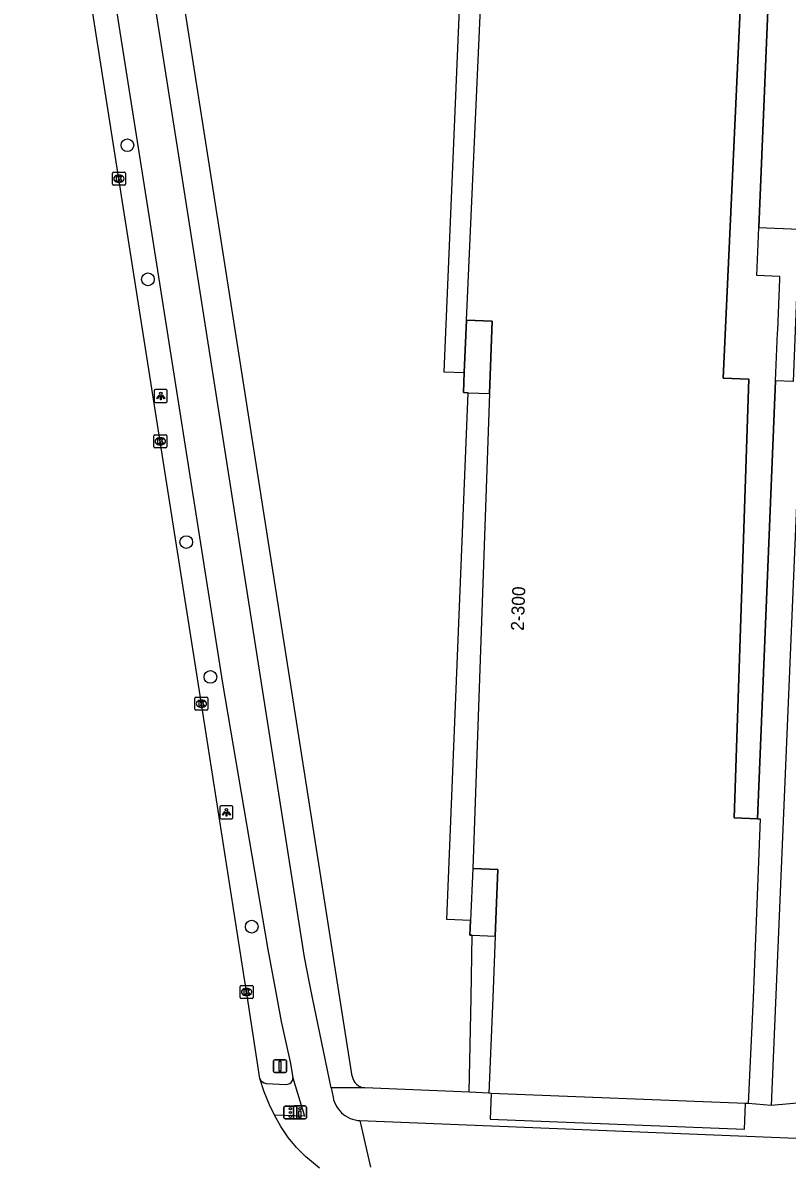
# Model space of a CAD drawing. Extents: x 160891 to 161384, y 386490 to 386907.
# Drawn here: x 160895.5 to 160954.4, y 386737.3 to 386825.1 of the extents above; entities that cross this region are included whole.
import ezdxf

# ---------------------------------------------------------------- set-up
doc = ezdxf.new("R2010")
doc.units = 0
for name, color, linetype in [('IMGEO_Boom', 7, 'Continuous'), ('IMGEO_Drukknoppaal', 7, 'Continuous'), ('IMGEO_Fietspad_gesloten', 7, 'Continuous'), ('IMGEO_Groenvoorziening', 7, 'Continuous'), ('IMGEO_Kolk', 7, 'Continuous'), ('IMGEO_Lichtpunt', 7, 'Continuous'), ('IMGEO_Pand', 7, 'Continuous'), ('IMGEO_Pand_nummerreeks', 7, 'Continuous'), ('IMGEO_Pand_overbouw', 7, 'Continuous'), ('IMGEO_Rijbaan_lokaal_gesloten', 7, 'Continuous'), ('IMGEO_Verkeersbordpaal', 7, 'Continuous'), ('IMGEO_Verkeersregelinstallatiepaal', 7, 'Continuous'), ('IMGEO_Voetpad_gesloten', 7, 'Continuous'), ('IMGEO_Voetpad_open', 7, 'Continuous')]:
    doc.layers.add(name, color=color, linetype=linetype)

msp = doc.modelspace()

# ---------------------------------------------------------------- linework, layer by layer
at = {"layer": 'IMGEO_Boom'}
for centre in [(160903.554, 386815.703), (160905.132, 386805.364), (160908.087, 386785.118), (160909.949, 386774.72), (160913.128, 386755.473)]:
    msp.add_circle(centre, 0.489, dxfattribs=at)
at = {"layer": 'IMGEO_Drukknoppaal'}
for p, q in [((160916.348, 386740.753), (160916.348, 386741.553)), ((160916.348, 386741.553), (160916.348, 386740.753)), ((160916.448, 386741.653), (160917.238, 386741.653)), ((160917.238, 386741.653), (160916.448, 386741.653)), ((160917.338, 386741.553), (160917.338, 386740.753)), ((160917.338, 386740.753), (160917.338, 386741.553)), ((160917.238, 386740.653), (160916.448, 386740.653)), ((160916.448, 386740.653), (160917.238, 386740.653))]:
    msp.add_line(p, q, dxfattribs=at)
msp.add_lwpolyline([(160916.918, 386741.278), (160916.918, 386740.778), (160916.768, 386740.778), (160916.768, 386741.278), (160916.918, 386741.278)], dxfattribs=at)
msp.add_circle((160916.843, 386741.443), 0.085, dxfattribs=at)
for centre, start, end in [((160916.448, 386741.553), 90, 180), ((160916.448, 386741.553), 90, 180), ((160917.238, 386741.553), 0, 90), ((160917.238, 386741.553), 360, 90), ((160916.448, 386740.753), 180, 270), ((160916.448, 386740.753), 180, 270), ((160917.238, 386740.753), 270, 0), ((160917.238, 386740.753), 270, 0)]:
    msp.add_arc(centre, 0.1, start, end, dxfattribs=at)
at = {"layer": 'IMGEO_Fietspad_gesloten'}
for points in [[(160919.245, 386743.063), (160917.807, 386750), (160917.572, 386751.136), (160917.197, 386753.124), (160907.589, 386814.399), (160899.722, 386864.375)], [(160897.273, 386860.565), (160897.429, 386859.589), (160904.689, 386813.559), (160910.872, 386774.235), (160914.38, 386753.725), (160915.067, 386750), (160915.406, 386748.161), (160916.107, 386744.917), (160916.31, 386743.822)], [(160916.31, 386743.822), (160917.205, 386740.862), (160914.891, 386740.934)], [(160919.245, 386743.063), (160919.397, 386742.327), (160919.443, 386742.134), (160919.505, 386741.946), (160919.584, 386741.764), (160919.68, 386741.59), (160919.79, 386741.425), (160919.915, 386741.27), (160920.052, 386741.128), (160920.203, 386740.998), (160920.364, 386740.882), (160920.534, 386740.781), (160920.714, 386740.696), (160920.9, 386740.627), (160921.091, 386740.575), (160921.286, 386740.54), (160921.46, 386740.524)], [(160921.46, 386740.524), (160922.279, 386736.94)], [(160921.46, 386740.524), (160955.08, 386739.168), (160992.282, 386737.671)]]:
    msp.add_lwpolyline(points, dxfattribs=at)
at = {"layer": 'IMGEO_Groenvoorziening'}
msp.add_lwpolyline([(160929.897, 386742.707), (160930.028, 386750), (160930.114, 386754.806), (160929.938, 386754.813), (160929.987, 386755.938), (160928.176, 386756.029), (160929.806, 386796.624), (160929.436, 386796.639), (160929.5, 386798.18)], dxfattribs=at)
at = {"layer": 'IMGEO_Kolk'}
for p, q in [((160902.398, 386812.687), (160902.398, 386813.539)), ((160902.473, 386813.613), (160903.325, 386813.613)), ((160902.886, 386813.393), (160902.911, 386813.393)), ((160903.399, 386813.539), (160903.399, 386812.687)), ((160903.325, 386812.613), (160902.473, 386812.613)), ((160902.909, 386812.833), (160902.884, 386812.833)), ((160905.586, 386792.452), (160905.586, 386793.304)), ((160905.661, 386793.378), (160906.513, 386793.378)), ((160906.074, 386793.158), (160906.099, 386793.158)), ((160906.587, 386793.304), (160906.587, 386792.452)), ((160906.513, 386792.378), (160905.661, 386792.378)), ((160906.097, 386792.598), (160906.072, 386792.598)), ((160908.751, 386772.229), (160908.751, 386773.081)), ((160908.826, 386773.155), (160909.678, 386773.155)), ((160909.239, 386772.935), (160909.264, 386772.935)), ((160909.752, 386773.081), (160909.752, 386772.229)), ((160909.678, 386772.155), (160908.826, 386772.155)), ((160909.262, 386772.375), (160909.237, 386772.375)), ((160912.236, 386750.014), (160912.236, 386750.866)), ((160912.311, 386750.94), (160913.163, 386750.94)), ((160912.724, 386750.72), (160912.749, 386750.72)), ((160913.237, 386750.866), (160913.237, 386750.014)), ((160913.163, 386749.94), (160912.311, 386749.94)), ((160912.747, 386750.16), (160912.722, 386750.16))]:
    msp.add_line(p, q, dxfattribs=at)
for points in [[(160902.398, 386812.687), (160902.398, 386813.539)], [(160902.473, 386813.613), (160903.325, 386813.613)], [(160902.719, 386813.313), (160902.842, 386813.313), (160902.842, 386813.162), (160902.972, 386813.313), (160903.136, 386813.313), (160902.99, 386813.162), (160903.143, 386812.913), (160902.991, 386812.913), (160902.906, 386813.077), (160902.842, 386813.01), (160902.842, 386812.913), (160902.719, 386812.913), (160902.719, 386813.313)], [(160903.399, 386813.539), (160903.399, 386812.687)], [(160903.325, 386812.613), (160902.473, 386812.613)], [(160905.586, 386792.452), (160905.586, 386793.304)], [(160905.661, 386793.378), (160906.513, 386793.378)], [(160905.907, 386793.078), (160906.03, 386793.078), (160906.03, 386792.927), (160906.16, 386793.078), (160906.324, 386793.078), (160906.178, 386792.927), (160906.331, 386792.678), (160906.179, 386792.678), (160906.094, 386792.842), (160906.03, 386792.775), (160906.03, 386792.678), (160905.907, 386792.678), (160905.907, 386793.078)], [(160906.587, 386793.304), (160906.587, 386792.452)], [(160906.513, 386792.378), (160905.661, 386792.378)], [(160908.751, 386772.229), (160908.751, 386773.081)], [(160908.826, 386773.155), (160909.678, 386773.155)], [(160909.072, 386772.855), (160909.195, 386772.855), (160909.195, 386772.704), (160909.325, 386772.855), (160909.489, 386772.855), (160909.343, 386772.704), (160909.496, 386772.455), (160909.344, 386772.455), (160909.259, 386772.619), (160909.195, 386772.552), (160909.195, 386772.455), (160909.072, 386772.455), (160909.072, 386772.855)], [(160909.752, 386773.081), (160909.752, 386772.229)], [(160909.678, 386772.155), (160908.826, 386772.155)], [(160912.236, 386750.014), (160912.236, 386750.866)], [(160912.311, 386750.94), (160913.163, 386750.94)], [(160912.557, 386750.64), (160912.68, 386750.64), (160912.68, 386750.489), (160912.81, 386750.64), (160912.974, 386750.64), (160912.828, 386750.489), (160912.981, 386750.24), (160912.829, 386750.24), (160912.744, 386750.404), (160912.68, 386750.337), (160912.68, 386750.24), (160912.557, 386750.24), (160912.557, 386750.64)], [(160913.237, 386750.866), (160913.237, 386750.014)], [(160913.163, 386749.94), (160912.311, 386749.94)]]:
    msp.add_lwpolyline(points, dxfattribs=at)
for centre, start, end in [((160902.475, 386813.537), 91.55205, 178.44795), ((160902.475, 386813.537), 91.55205, 178.44795), ((160903.323, 386813.537), 1.55205, 88.44795), ((160903.323, 386813.537), 1.55205, 88.44795), ((160902.475, 386812.689), 181.55205, 268.44795), ((160902.475, 386812.689), 181.55205, 268.44795), ((160903.323, 386812.689), 271.55205, 358.44795), ((160903.323, 386812.689), 271.55205, 358.44795), ((160905.663, 386793.302), 91.55205, 178.44795), ((160905.663, 386793.302), 91.55205, 178.44795), ((160906.511, 386793.302), 1.55205, 88.44795), ((160906.511, 386793.302), 1.55205, 88.44795), ((160905.663, 386792.454), 181.55205, 268.44795), ((160905.663, 386792.454), 181.55205, 268.44795), ((160906.511, 386792.454), 271.55205, 358.44795), ((160906.511, 386792.454), 271.55205, 358.44795), ((160908.828, 386773.079), 91.55205, 178.44795), ((160908.828, 386773.079), 91.55205, 178.44795), ((160909.676, 386773.079), 1.55205, 88.44795), ((160909.676, 386773.079), 1.55205, 88.44795), ((160908.828, 386772.231), 181.55205, 268.44795), ((160908.828, 386772.231), 181.55205, 268.44795), ((160909.676, 386772.231), 271.55205, 358.44795), ((160909.676, 386772.231), 271.55205, 358.44795), ((160912.313, 386750.864), 91.55205, 178.44795), ((160912.313, 386750.864), 91.55205, 178.44795), ((160913.161, 386750.864), 1.55205, 88.44795), ((160913.161, 386750.864), 1.55205, 88.44795), ((160912.313, 386750.016), 181.55205, 268.44795), ((160912.313, 386750.016), 181.55205, 268.44795), ((160913.161, 386750.016), 271.55205, 358.44795), ((160913.161, 386750.016), 271.55205, 358.44795)]:
    msp.add_arc(centre, 0.0765, start, end, dxfattribs=at)
for centre, major_axis, ratio, start_param, end_param in [((160902.885, 386813.113), (-0.387, 0.002), 0.722429, 4.712389, 7.853982), ((160902.91, 386813.113), (-0.39, 0.002), 0.717154, 1.570796, 4.712389), ((160906.073, 386792.878), (-0.387, 0.002), 0.722429, 4.712389, 7.853982), ((160906.098, 386792.878), (-0.39, 0.002), 0.717154, 1.570796, 4.712389), ((160909.238, 386772.655), (-0.387, 0.002), 0.722429, 4.712389, 7.853982), ((160909.263, 386772.655), (-0.39, 0.002), 0.717154, 1.570796, 4.712389), ((160912.723, 386750.44), (-0.387, 0.002), 0.722429, 4.712389, 7.853982), ((160912.748, 386750.44), (-0.39, 0.002), 0.717154, 1.570796, 4.712389)]:
    msp.add_ellipse(centre, major_axis=major_axis, ratio=ratio, start_param=start_param, end_param=end_param, dxfattribs=at)
at = {"layer": 'IMGEO_Lichtpunt'}
for p, q in [((160905.623, 386796.78), (160905.623, 386795.973)), ((160905.623, 386796.78), (160905.623, 386795.973)), ((160906.525, 386796.875), (160905.717, 386796.875)), ((160906.525, 386796.875), (160905.717, 386796.875)), ((160906.619, 386795.973), (160906.619, 386796.78)), ((160906.619, 386795.973), (160906.619, 386796.78)), ((160905.717, 386795.879), (160906.525, 386795.879)), ((160905.717, 386795.879), (160906.525, 386795.879)), ((160910.678, 386764.694), (160910.678, 386763.887)), ((160910.678, 386764.694), (160910.678, 386763.887)), ((160911.58, 386764.789), (160910.772, 386764.789)), ((160911.58, 386764.789), (160910.772, 386764.789)), ((160911.674, 386763.887), (160911.674, 386764.694)), ((160911.674, 386763.887), (160911.674, 386764.694)), ((160910.772, 386763.793), (160911.58, 386763.793)), ((160910.772, 386763.793), (160911.58, 386763.793))]:
    msp.add_line(p, q, dxfattribs=at)
for points in [[(160905.997, 386796.444), (160906.036, 386796.416), (160905.848, 386796.154), (160905.81, 386796.181), (160905.997, 386796.444)], [(160906.099, 386796.396), (160906.146, 386796.396), (160906.146, 386796.074), (160906.099, 386796.074), (160906.099, 386796.396)], [(160906.209, 386796.416), (160906.247, 386796.443), (160906.434, 386796.181), (160906.395, 386796.153), (160906.209, 386796.416)], [(160911.052, 386764.358), (160911.091, 386764.33), (160910.903, 386764.068), (160910.865, 386764.095), (160911.052, 386764.358)], [(160911.154, 386764.31), (160911.201, 386764.31), (160911.201, 386763.988), (160911.154, 386763.988), (160911.154, 386764.31)], [(160911.264, 386764.33), (160911.302, 386764.357), (160911.489, 386764.095), (160911.45, 386764.067), (160911.264, 386764.33)]]:
    msp.add_lwpolyline(points, dxfattribs=at)
for centre in [(160906.122, 386796.578), (160911.177, 386764.492)]:
    msp.add_circle(centre, 0.0994, dxfattribs=at)
for centre, start, end in [((160905.717, 386796.78), 90, 180), ((160905.717, 386796.78), 90, 180), ((160906.525, 386796.78), 0, 90), ((160906.525, 386796.78), 0, 90), ((160905.717, 386795.973), 180, 270), ((160905.717, 386795.973), 180, 270), ((160906.525, 386795.973), 270, 0), ((160906.525, 386795.973), 270, 360), ((160910.772, 386764.694), 90, 180), ((160910.772, 386764.694), 90, 180), ((160911.58, 386764.694), 0, 90), ((160911.58, 386764.694), 0, 90), ((160910.772, 386763.887), 180, 270), ((160910.772, 386763.887), 180, 270), ((160911.58, 386763.887), 270, 0), ((160911.58, 386763.887), 270, 360)]:
    msp.add_arc(centre, 0.0946, start, end, dxfattribs=at)
at = {"layer": 'IMGEO_Pand'}
for points in [[(160929.668, 386802.21), (160932.347, 386861.777), (160934.345, 386861.699), (160934.451, 386864.398), (160941.654, 386864.075), (160941.548, 386861.376), (160943.509, 386861.288), (160952.319, 386860.893), (160952.148, 386856.549), (160954.129, 386856.46), (160953.788, 386847.794)], [(160952.108, 386763.787), (160950.315, 386763.859), (160951.446, 386797.676), (160949.448, 386797.758), (160951.78, 386847.873), (160953.788, 386847.794)], [(160929.668, 386802.21), (160931.656, 386802.139), (160931.458, 386796.556), (160930.162, 386759.955), (160932.106, 386759.876), (160931.896, 386754.732), (160931.703, 386750), (160931.403, 386742.634)], [(160952.108, 386763.787), (160952.32, 386763.778), (160951.772, 386750), (160951.385, 386741.835)], [(160951.385, 386741.835), (160951.188, 386741.843), (160931.578, 386742.627), (160931.403, 386742.634)]]:
    msp.add_lwpolyline(points, dxfattribs=at)
at = {"layer": 'IMGEO_Pand_overbouw'}
for points in [[(160953.788, 386847.794), (160951.78, 386847.873), (160949.448, 386797.758), (160951.446, 386797.676), (160950.315, 386763.859), (160952.108, 386763.787), (160953.498, 386797.543), (160953.65, 386801.238), (160953.658, 386801.438), (160953.82, 386805.388), (160953.828, 386805.588), (160952.045, 386805.661), (160952.198, 386809.36)], [(160929.668, 386802.21), (160929.5, 386798.18), (160929.436, 386796.639), (160929.806, 386796.624), (160931.458, 386796.556), (160931.656, 386802.139)], [(160931.896, 386754.732), (160932.106, 386759.876), (160930.162, 386759.955), (160929.987, 386755.938), (160929.938, 386754.813), (160930.114, 386754.806)], [(160931.578, 386742.627), (160931.495, 386740.644), (160951.101, 386739.86), (160951.188, 386741.843)]]:
    msp.add_lwpolyline(points, close=True, dxfattribs=at)
at = {"layer": 'IMGEO_Rijbaan_lokaal_gesloten'}
for points in [[(160913.758, 386743.775), (160912.804, 386750), (160912.737, 386750.44), (160909.252, 386772.655), (160906.087, 386792.878), (160902.899, 386813.113), (160898.944, 386838.332), (160895.937, 386857.577), (160895.636, 386859.48), (160895.508, 386860.258), (160895.489, 386860.369)], [(160914.891, 386740.934), (160914.487, 386741.731), (160914.076, 386742.739), (160913.758, 386743.775)], [(160918.361, 386736.864), (160918.036, 386737.106), (160917.275, 386737.753), (160916.574, 386738.465), (160915.94, 386739.237), (160915.378, 386740.062), (160914.891, 386740.934)]]:
    msp.add_lwpolyline(points, dxfattribs=at)
at = {"layer": 'IMGEO_Verkeersbordpaal'}
for p, q in [((160914.813, 386744.323), (160914.813, 386745.123)), ((160914.813, 386745.123), (160914.813, 386744.323)), ((160914.913, 386745.223), (160915.703, 386745.223)), ((160915.703, 386745.223), (160914.913, 386745.223)), ((160915.803, 386745.123), (160915.803, 386744.323)), ((160915.803, 386744.323), (160915.803, 386745.123)), ((160915.703, 386744.223), (160914.913, 386744.223)), ((160914.913, 386744.223), (160915.703, 386744.223))]:
    msp.add_line(p, q, dxfattribs=at)
msp.add_lwpolyline([(160915.233, 386745.098), (160915.383, 386745.098), (160915.383, 386744.348), (160915.233, 386744.348), (160915.233, 386745.098)], dxfattribs=at)
for centre, start, end in [((160914.913, 386745.123), 90, 180), ((160914.913, 386745.123), 90, 180), ((160915.703, 386745.123), 0, 90), ((160915.703, 386745.123), 360, 90), ((160914.913, 386744.323), 180, 270), ((160914.913, 386744.323), 180, 270), ((160915.703, 386744.323), 270, 0), ((160915.703, 386744.323), 270, 0)]:
    msp.add_arc(centre, 0.1, start, end, dxfattribs=at)
at = {"layer": 'IMGEO_Verkeersregelinstallatiepaal'}
for p, q in [((160915.614, 386740.751), (160915.614, 386741.551)), ((160915.614, 386741.551), (160915.614, 386740.751)), ((160915.714, 386741.651), (160916.504, 386741.651)), ((160916.504, 386741.651), (160915.714, 386741.651)), ((160916.604, 386741.551), (160916.604, 386740.751)), ((160916.604, 386740.751), (160916.604, 386741.551)), ((160916.504, 386740.651), (160915.714, 386740.651)), ((160915.714, 386740.651), (160916.504, 386740.651))]:
    msp.add_line(p, q, dxfattribs=at)
for centre in [(160916.109, 386741.441), (160916.109, 386741.151), (160916.109, 386740.861)]:
    msp.add_circle(centre, 0.085, dxfattribs=at)
for centre, start, end in [((160915.714, 386741.551), 90, 180), ((160915.714, 386741.551), 90, 180), ((160916.504, 386741.551), 0, 90), ((160916.504, 386741.551), 360, 90), ((160915.714, 386740.751), 180, 270), ((160915.714, 386740.751), 180, 270), ((160916.504, 386740.751), 270, 0), ((160916.504, 386740.751), 270, 0)]:
    msp.add_arc(centre, 0.1, start, end, dxfattribs=at)
at = {"layer": 'IMGEO_Voetpad_gesloten'}
for points in [[(160921.858, 386743.044), (160919.245, 386743.063)], [(160929.897, 386742.707), (160921.858, 386743.044)], [(160931.403, 386742.634), (160929.897, 386742.707)], [(160958.336, 386742.153), (160953.158, 386741.685)], [(160953.158, 386741.685), (160951.385, 386741.835)]]:
    msp.add_lwpolyline(points, dxfattribs=at)
at = {"layer": 'IMGEO_Voetpad_open'}
for points in [[(160920.871, 386743.948), (160919.923, 386750), (160909.808, 386814.589), (160901.002, 386870.642)], [(160930.929, 386869.413), (160927.927, 386798.235), (160929.5, 386798.18)], [(160953.788, 386847.794), (160952.198, 386809.36), (160955.314, 386809.236), (160954.852, 386797.5), (160953.498, 386797.543), (160952.108, 386763.787)], [(160956.276, 386815.366), (160953.158, 386741.685)], [(160929.5, 386798.18), (160929.668, 386802.21)], [(160914.246, 386743.387), (160915.791, 386743.32)]]:
    msp.add_lwpolyline(points, dxfattribs=at)
for centre, radius, start, end in [((160914.327, 386743.989), 0.608, 200.64836, 262.37649), ((160915.811, 386743.819), 0.499, 267.70354, 0.38865), ((160921.926, 386744.109), 1.067, 188.65599, 266.37045)]:
    msp.add_arc(centre, radius, start, end, dxfattribs=at)

# ---------------------------------------------------------------- texts
at = {"layer": 'IMGEO_Pand_nummerreeks'}
msp.add_text('2-300', height=1, rotation=87.97164, dxfattribs=at).set_placement((160934.092, 386778.259))

doc.saveas('drawing.dxf')
